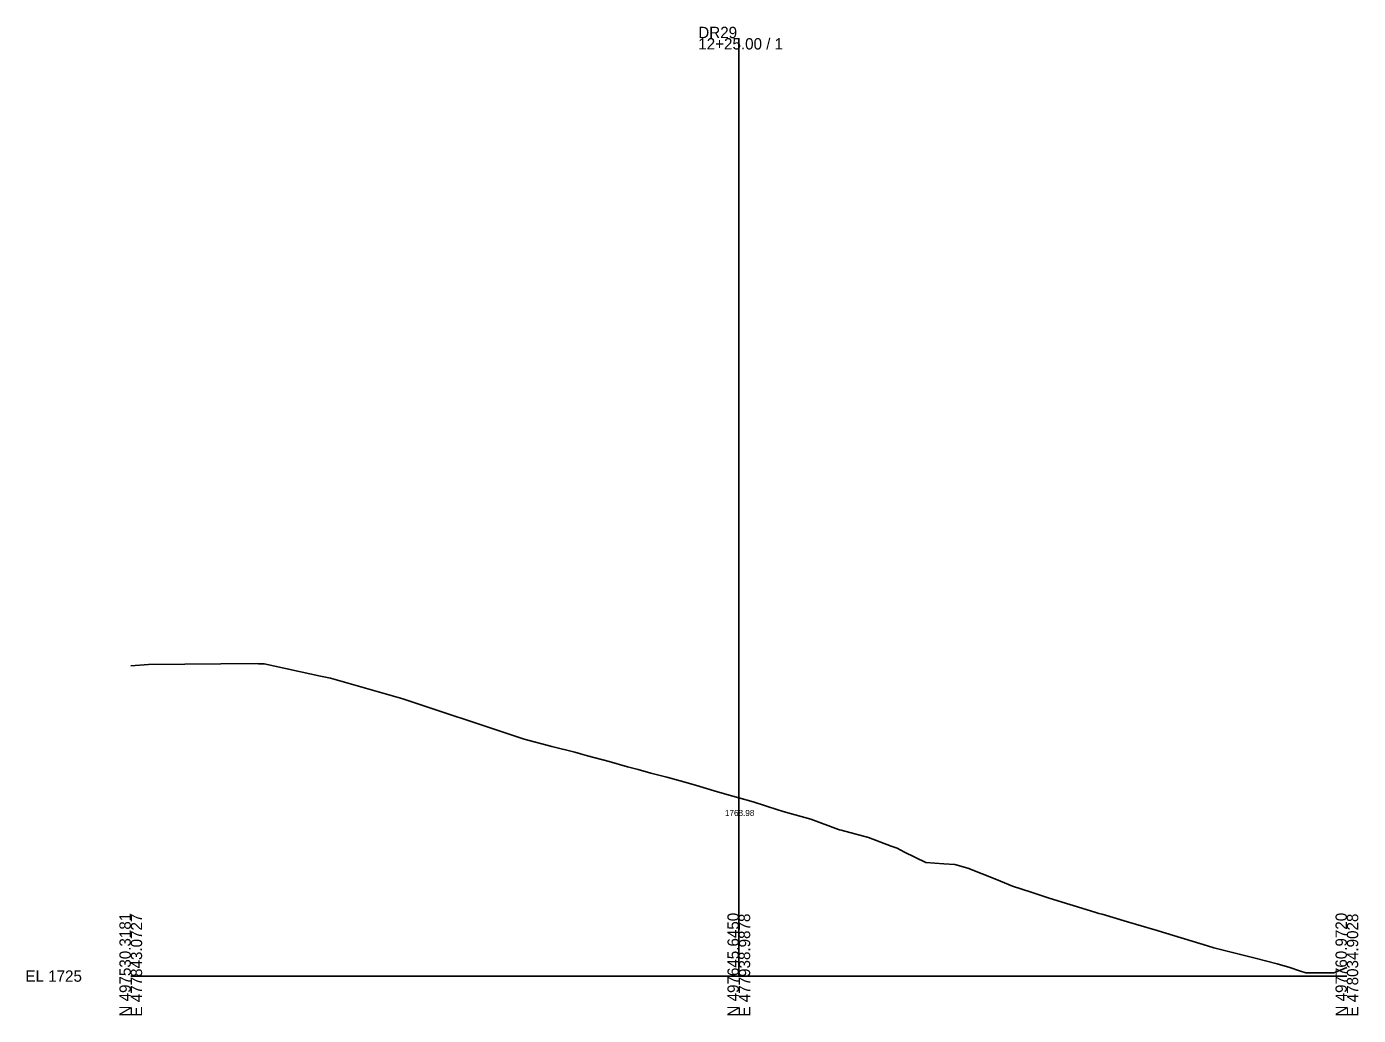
# Model space of a CAD drawing. Extents: x -26 to 303, y -10 to 4734.
# Drawn here: x -25.7 to 302.8, y 4490.3 to 4734.2 of the extents above; entities that cross this region are included whole.
import ezdxf

# ---------------------------------------------------------------- set-up
doc = ezdxf.new("R2010")
doc.units = 0
for name, color, linetype in [('Exist Cross Section Cell', 7, 'Continuous'), ('Exist XS Center Line Elevation Label', 7, 'Continuous'), ('Exist XS Ground Line', 7, 'Continuous')]:
    doc.layers.add(name, color=color, linetype=linetype)

msp = doc.modelspace()

# ---------------------------------------------------------------- linework, layer by layer
at = {"layer": 'Exist Cross Section Cell'}
for p, q in [((150, 4500), (150, 4731.35)), ((0, 4500), (150, 4500)), ((150, 4500), (300, 4500))]:
    msp.add_line(p, q, dxfattribs=at)
at = {"layer": 'Exist XS Ground Line'}
msp.add_line((94.84, 4559.15), (97.03, 4558.43), dxfattribs=at)
for points in [[(0, 4576.56), (4.39, 4576.85), (31.17, 4577.12), (31.47, 4577.05), (32.87, 4577.01), (46.79, 4573.99), (49.27, 4573.45), (67.11, 4568.37), (94.84, 4559.15)], [(97.03, 4558.43), (103.84, 4556.66), (109.51, 4555.19), (110.94, 4554.79), (112.67, 4554.3), (118.05, 4552.93), (122.52, 4551.63), (125.15, 4550.98), (128.31, 4550.06), (132.25, 4549.03), (135.53, 4548.12), (139.35, 4547.08), (143.95, 4545.71), (146.45, 4544.97), (148.53, 4544.39), (150, 4543.98), (153.56, 4542.98), (159.6, 4541.01), (160.66, 4540.67), (161.54, 4540.41), (167.76, 4538.71), (174.55, 4536.16), (174.86, 4536.06), (175.24, 4535.96), (181.97, 4534.18), (187.56, 4532.07), (189.07, 4531.53), (190.88, 4530.57), (196.17, 4528.01), (200.57, 4527.7), (203.27, 4527.48), (206.52, 4526.65), (213.58, 4523.86), (217.48, 4522.18), (222.16, 4520.67), (224.58, 4519.9), (226.59, 4519.22), (231.68, 4517.62), (237.8, 4515.76), (238.78, 4515.47), (239.6, 4515.24), (245.89, 4513.41), (252.61, 4511.41), (252.99, 4511.3), (253.45, 4511.15), (265.62, 4507.45), (267.19, 4507), (277.34, 4504.43), (282.78, 4503.03), (285.97, 4502.1), (288.28, 4501.29), (289.86, 4500.78), (292.9, 4500.78), (293.7, 4500.78), (296.77, 4500.8), (297.99, 4501.26), (300, 4502.13)]]:
    msp.add_lwpolyline(points, dxfattribs=at)

# ---------------------------------------------------------------- texts
at = {"layer": 'Exist Cross Section Cell'}
for s, p in [('DR29', (140, 4731.35)), ('12+25.00 / 1', (140, 4728.55)), ('EL 1725', (-26, 4498.6))]:
    msp.add_text(s, height=2.8, dxfattribs=at).set_placement(p)
for s, p in [('N 497530.3181', (0, 4490)), ('E 477843.0727', (2.8, 4490)), ('N 497645.6450', (150, 4490)), ('E 477938.9878', (152.8, 4490)), ('N 497760.9720', (300, 4490)), ('E 478034.9028', (302.8, 4490))]:
    msp.add_text(s, height=2.8, rotation=90, dxfattribs=at).set_placement(p)
at = {"layer": 'Exist XS Center Line Elevation Label'}
msp.add_text('1768.98', height=1.5, dxfattribs=at).set_placement((146.58, 4539.48))

doc.saveas('drawing.dxf')
